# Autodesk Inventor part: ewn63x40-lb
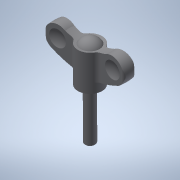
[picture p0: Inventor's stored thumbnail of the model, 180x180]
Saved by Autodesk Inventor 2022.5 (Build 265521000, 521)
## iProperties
Created: 2017-05
Part Number: ewn63x40-lb
Material: 一般
Document SubType Name: Modeling
Designer: imaocorp
Density: 1 g/cm^3
Appearance: 既定
Author: imaocorp
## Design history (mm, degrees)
node "ewn63x40-lb.x_t1"
node "ewn63x40-lb"
node "Base1"
